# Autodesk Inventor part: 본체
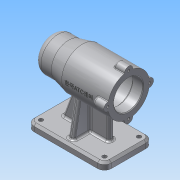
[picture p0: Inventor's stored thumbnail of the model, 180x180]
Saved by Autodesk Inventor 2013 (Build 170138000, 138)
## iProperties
Created: 2019-07
Part Number: 본체
Material: 알루미늄 6061
Document SubType Name: Modeling
Designer: Administrator
Density: 2.71 g/cm^3
Mass: 642.657 g
Surface Area: 659.642 cm^2
Volume: 237.143 cm^3
Author: Administrator
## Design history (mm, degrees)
sketch "스케치1"
  geometry: L1 (-56, 0)-(56, 0); L2 (56, 0)-(56, 30); L3 (56, 30)-(-11, 30); L4 (-11, 30)-(-31, 25); L5 (-31, 25)-(-56, 25); L6 (-56, 25)-(-56, 0); 2 further points
  constraints: 12 end point, 2 parallel, 2 perpendicular, 1 coincident, 1 horizontal, 1 midpoint
  dimensions: "d0" = 60 diameter of L3 L1; "d2" = 45 horizontal distance of L3.end L5.end; "d3" = 25 distance of L5.end L4.end; "d4" = 50 diameter of L5 L1; "d5" = 112 distance of L1.start L1.end
revolve "회전1" sketch "스케치1" stored, may be unused: angle "d6" = 90 deg
node "작업 평면1"
sketch "스케치2"
  geometry: L1 (56, -35)-(-56, -35); L2 (-56, -35)-(-56, 35); L3 (-56, 35)-(56, 35); L4 (56, 35)-(56, -35); L5 (56, -35)-(-56, 35); L6 (-56, -35)-(56, 35); 1 further point
  constraints: 12 end point, 2 midpoint, 2 parallel, 1 horizontal, 1 perpendicular
  dimensions: "d8" = 112 distance of L2.end L3.end; "d10" = 70 distance of L3.end L1.start
extrude "돌출1" join sketch "스케치2" distance "d11" = 10; taper "d12" = 0 deg
sketch "스케치5"
  geometry: C1 r 6 at (0, 30); 1 further point
  constraints: 2 vertical alignment, 1 centre point, 1 other
  dimensions: "d31" = 12 diameter of C1
extrude "돌출3" join sketch "스케치5" distance "d32" = 16; taper "d33" = 0 deg
sketch "스케치6"
  geometry: A1 r 6 centre (0, 0) between (5.97, -0.6) and (-5.97, -0.6) reference; A2 r 6 centre (-30, -30) between (-29.4, -24.03) and (-29.4, -35.97) reference; A3 r 6 centre (0, -60) between (-5.97, -59.4) and (5.97, -59.4) reference; A4 r 6 centre (30, -30) between (29.4, -35.97) and (29.4, -24.03) reference
hole "구멍1" sketch "스케치6" at (0, 0), (-30, -30), (0, -60), (30, -30) diameter "d37" = 3.242; stored, may be unused: countersink angle "d41" = 90 deg, drill point angle "d43" = 118 deg; dims "d38" = 8, "d39" = 4, "d40" = 2, "d42" = 11
sketch "스케치7"
  geometry: L1 (-56, -25)-(-56, 25) reference; L2 (-56, 25)-(-31, 25) reference; L3 (-31, 25)-(-11, 30) reference; L4 (-11, 30)-(40, 30) reference; L5 (40, 30)-(40, 36) reference; L6 (40, 36)-(56, 36) reference; L7 (56, 36)-(56, 31.621) reference; L8 (56, 31.621)-(45, 31.621) reference; L9 (45, 31.621)-(44.026, 30) reference; L10 (44.026, 30)-(45, 28.379) reference; L11 (45, 28.379)-(56, 28.379) reference; L12 (56, 28.379)-(56, -28.379) reference; L13 (56, -28.379)-(45, -28.379) reference; L14 (45, -28.379)-(44.026, -30) reference; L15 (44.026, -30)-(45, -31.621) reference; L16 (45, -31.621)-(56, -31.621) reference; L17 (56, -31.621)-(56, -36) reference; L18 (56, -36)-(40, -36) reference; L19 (40, -36)-(40, -30) reference; L20 (40, -30)-(-11, -30) reference; L21 (-56, -70)-(56, -70) reference; L22 (56, -70)-(56, -80) reference; L23 (56, -80)-(-56, -80) reference; L24 (-56, -80)-(-56, -70) reference; L25 (-11, -30)-(-31, -25) reference; L26 (-31, -25)-(-56, -25) reference; L27 (-50, 0)-(56, 0); L28 (-50, 0)-(-50, 10.5); L29 (-50, 10.5)-(-47, 10.5); L30 (-47, 10.5)-(-47, 16); L31 (-47, 16)-(-43, 16); L32 (-43, 16)-(-43, 17.5); L33 (-43, 17.5)-(-25, 17.5); L34 (-25, 17.5)-(-25, 21); L35 (-25, 21)-(-13, 21); L36 (-13, 21)-(-13, 24); L37 (-13, 24)-(41, 24); L38 (41, 24)-(41, 21); L39 (41, 21)-(56, 21); L40 (56, 21)-(56, 0); 1 further point
  constraints: 28 end point, 10 parallel, 3 perpendicular, 2 point on line, 1 midpoint
  dimensions: "d44" = 3 distance of L28.end L29.end; "d46" = 4 distance of L30.end L31.end; "d47" = 15 distance of L38.end L39.end; "d48" = 54 distance of L36.end L37.end; "d49" = 12 distance of L34.end L35.end; "d50" = 18 distance of L32.end L33.end; "d53" = 21 diameter of L29 L27; "d54" = 32 diameter of L31 L27; "d55" = 35 diameter of L33 L27; "d57" = 42 diameter of L35 L27; "d58" = 48 diameter of L37 L27; "d59" = 42 diameter of L39 L27
revolve "회전2" sketch "스케치7" stored, may be unused: angle "d60" = 90 deg
fillet "모깎기1" dims "d61" = 10
sketch "스케치8"
  geometry: A1 r 10 centre (46, 25) between (56, 25) and (46, 35) reference; A2 r 10 centre (-46, 25) between (-46, 35) and (-56, 25) reference; A3 r 10 centre (-46, -25) between (-56, -25) and (-46, -35) reference; A4 r 10 centre (46, -25) between (46, -35) and (56, -25) reference; 1 further point
hole "구멍2" sketch "스케치8" at (46, 25), (-46, 25), (-46, -25), (46, -25) diameter "d62" = 6; stored, may be unused: countersink angle "d66" = 90 deg, drill point angle "d68" = 118 deg; dims "d63" = 8, "d64" = 4, "d65" = 2, "d67" = 11
chamfer "모따기1" distance "d69" = 3; stored, may be unused: second distance "d70" = 2, angle "d71" = 45 deg
fillet "모깎기2" dims "d72" = 0.3
fillet "모깎기3" dims "d73" = 10
sketch "스케치9"
  geometry: L1 (0, 4)-(31, 4); L2 (31, 4)-(31, -4); L3 (31, -4)-(0, -4); L4 (0, -4)-(0, 4); L5 (56, -25)-(56, 25) reference; 2 further points
  constraints: 8 end point, 2 parallel, 1 coincident, 1 horizontal, 1 midpoint, 1 perpendicular
  dimensions: "d80" = 25 distance between parallel lines of L5 L2; "d81" = 8 distance of L1.end L2.end
extrude "돌출4" join sketch "스케치9" stored distance "d82" = 16; taper "d83" = 0 deg
sketch "스케치10"
  geometry: L1 (-70, -32)-(-73, -35) reference; L2 (-73, -35)-(-80, -35) reference; L3 (-80, -35)-(-80, 35) reference; L4 (-80, 35)-(-73, 35) reference; L5 (-73, 35)-(-70, 32) reference; L6 (-70, 32)-(-70, 4) reference; L7 (-70, 4)-(-70, -4) reference; L8 (-70, -4)-(-70, -32) reference; L9 (-70, 4)-(-29.732, 4) reference; L10 (-29.732, -4)-(-70, -4) reference; L11 (-70, 28)-(-22.666, 19.654); C1 r 24 at (0, 0) reference; A1 r 30 centre (0, 0) between (-29.732, -4) and (-29.732, 4) reference; A2 r 30 centre (0, 0) between (-29.732, 4) and (-29.732, -4) reference; 1 further point
  constraints: 2 end point, 1 point on circle, 1 point on line
  dimensions: "d84" = 100 deg angle of L3 L11; "d85" = 7 distance from line of L4 L11.start
  node "절단 모서리 투영4"
sketch "스케치11"
  geometry: L1 (40, 36)-(56, 36) reference; L2 (56, 36)-(56, 31.621) reference; L3 (56, 31.621)-(45, 31.621) reference; L4 (45, 31.621)-(44.026, 30) reference; L5 (44.026, 30)-(45, 28.379) reference; L6 (45, 28.379)-(56, 28.379) reference; L7 (56, 28.379)-(56, 21) reference; L8 (56, 21)-(41, 21) reference; L9 (41, 21)-(41, 24) reference; L10 (41, 24)-(-13, 24) reference; L11 (-13, 24)-(-13, 21) reference; L12 (-13, 21)-(-24.7, 21) reference; L13 (-25, 20.7)-(-25, 17.5) reference; L14 (-25, 17.5)-(-42.7, 17.5) reference; L15 (-43, 17.2)-(-43, 16) reference; L16 (-43, 16)-(-46.7, 16) reference; L17 (-47, 15.7)-(-47, 10.5) reference; L18 (-47, 10.5)-(-50, 10.5) reference; L19 (-50, 10.5)-(-50, -10.5) reference; L20 (-50, -10.5)-(-47, -10.5) reference; L21 (-47, -10.5)-(-47, -15.7) reference; L22 (-46.7, -16)-(-43, -16) reference; L23 (-43, -16)-(-43, -17.2) reference; L24 (-42.7, -17.5)-(-25, -17.5) reference; L25 (-25, -17.5)-(-25, -20.7) reference; L26 (-24.7, -21)-(-13, -21) reference; L27 (-13, -21)-(-13, -24) reference; L28 (-13, -24)-(41, -24) reference; L29 (41, -24)-(41, -21) reference; L30 (41, -21)-(56, -21) reference; L31 (56, -21)-(56, -28.379) reference; L32 (56, -28.379)-(45, -28.379) reference; L33 (45, -28.379)-(44.026, -30) reference; L34 (44.026, -30)-(45, -31.621) reference; L35 (45, -31.621)-(56, -31.621) reference; L36 (56, -31.621)-(56, -36) reference; L37 (56, -36)-(40, -36) reference; L38 (40, -36)-(40, -30) reference; L39 (40, -30)-(31, -30) reference; L40 (31, -30)-(31, -70) reference; L41 (31, -70)-(53, -70) reference; L42 (53, -70)-(56, -73) reference; L43 (56, -73)-(56, -80) reference; L44 (56, -80)-(-56, -80) reference; L45 (-56, -80)-(-56, -73) reference; L46 (-56, -73)-(-53, -70) reference; L47 (-53, -70)-(0, -70) reference; L48 (0, -70)-(0, -30) reference; L49 (0, -30)-(-11, -30) reference; L50 (-11, -30)-(-31, -25) reference; L51 (-31, -25)-(-46, -25) reference; L52 (-56, -15)-(-56, 15) reference; L53 (-46, 25)-(-31, 25) reference; L54 (-31, 25)-(-11, 30) reference; L55 (-11, 30)-(40, 30) reference; L56 (40, 30)-(40, 36) reference; L57 (-36, -70)-(-20.57, -27.607); A1 r 0.3 centre (-24.7, 20.7) between (-24.7, 21) and (-25, 20.7) reference; A2 r 0.3 centre (-42.7, 17.2) between (-42.7, 17.5) and (-43, 17.2) reference; A3 r 0.3 centre (-46.7, 15.7) between (-46.7, 16) and (-47, 15.7) reference; A4 r 0.3 centre (-46.7, -15.7) between (-47, -15.7) and (-46.7, -16) reference; A5 r 0.3 centre (-42.7, -17.2) between (-43, -17.2) and (-42.7, -17.5) reference; A6 r 0.3 centre (-24.7, -20.7) between (-25, -20.7) and (-24.7, -21) reference; A7 r 10 centre (-46, -15) between (-56, -15) and (-46, -25) reference; A8 r 10 centre (-46, 15) between (-46, 25) and (-56, 15) reference; 1 further point
  constraints: 2 end point, 2 point on line
  dimensions: "d86" = 110 deg angle of L47 L57; "d87" = 20 distance from line of L57.start L45
feature "리브2" sketch "스케치11" dims "d88" = 1, "d89" = 8, "d90" = 0, "d91" = 0, "d92" = 1, "d93" = 1
feature "리브3" dims "d94" = 1, "d95" = 8, "d96" = 0, "d97" = 0, "d98" = 1, "d99" = 1
fillet "모깎기7" dims "d100" = 3
chamfer "모따기2" distance "d101" = 1; stored, may be unused: second distance "d102" = 2, angle "d103" = 45 deg
fillet "모깎기8" dims "d104" = 3
node "작업 평면2"
sketch "스케치12"
  geometry: L1 (102, 85.97)-(102, 109.4) reference; 2 further points
  constraints: 1 horizontal alignment, 1 other
  dimensions: "d106" = 42 distance from line of point (60, 80) L1
feature "엠보싱1" sketch "스케치12" dims "d107" = 0.5, "d108" = 0
fillet "모깎기9" dims "d109" = 3
fillet "모깎기10" dims "d110" = 1
fillet "모깎기11" dims "d111" = 3
node "솔리드1"
pattern_circular "원형 패턴1" dims angle "d35" = 360 deg
mirror "대칭2"
node "절단 모서리 투영3"
node "절단 모서리 투영5"
other parameters: "d105" = 103.5
